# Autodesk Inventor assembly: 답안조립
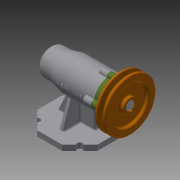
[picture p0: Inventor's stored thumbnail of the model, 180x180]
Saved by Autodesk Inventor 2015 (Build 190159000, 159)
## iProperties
Created: 2019-12
Part Number: 답안조립
Document SubType Name: Assembly
Designer: now
Author: now
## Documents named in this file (12)
- C:\Users\now\Desktop\강민정\491204V1042\답안조립.iam
- C:\Users\now\Desktop\강민정\491204V1042\Ű 5 x 5 x 16.ipt
- C:\Users\now\Desktop\강민정\491204V1042\V벨트풀리.ipt
- C:\Users\now\Desktop\강민정\491204V1042\멈춤나사 M3.ipt
- C:\Users\now\Desktop\강민정\491204V1042\베어링 6004.ipt
- C:\Users\now\Desktop\강민정\491204V1042\베어링 51202.ipt
- C:\Users\now\Desktop\강민정\491204V1042\본체.ipt
- C:\Users\now\Desktop\강민정\491204V1042\볼트 M4.ipt
- C:\Users\now\Desktop\강민정\491204V1042\어댑터슬리브.ipt
- C:\Users\now\Desktop\강민정\491204V1042\오일 실.ipt
- C:\Users\now\Desktop\강민정\491204V1042\축.ipt
- C:\Users\now\Desktop\강민정\491204V1042\커버.ipt
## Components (2 placed, 2 different names)
1. Ű 5 x 5 x 16:1 — 각도:1, 각도:2
2. V벨트풀리:1 — 각도:2
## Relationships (2: Angle 2)
- 각도:1 [Angle]: Ű 5 x 5 x 16:1
- 각도:2 [Angle]: Ű 5 x 5 x 16:1 ↔ V벨트풀리:1
